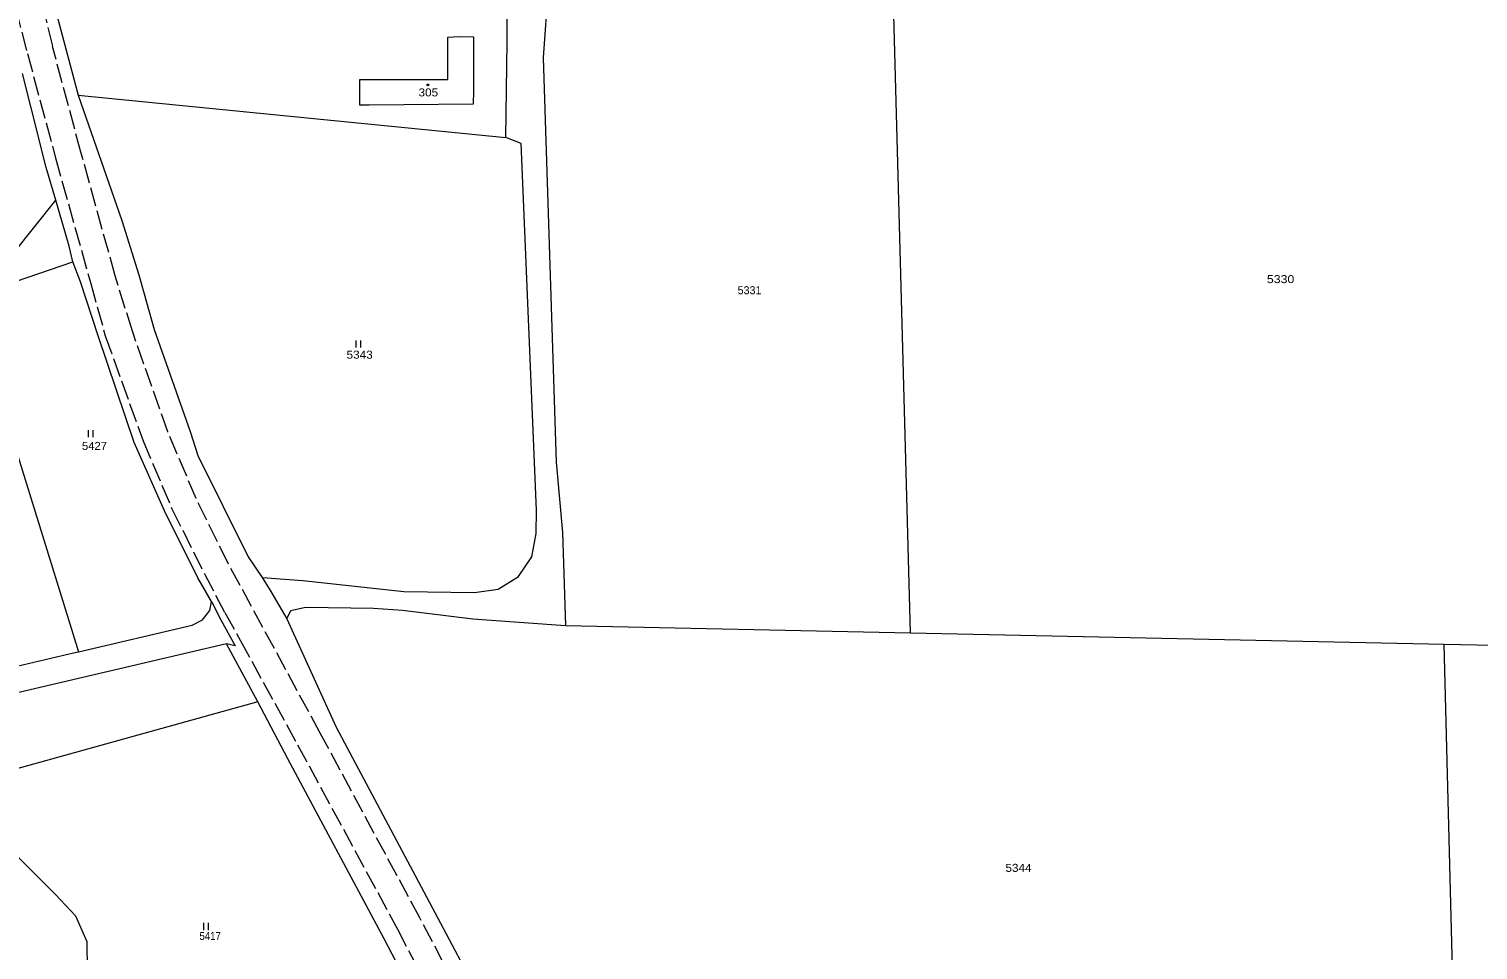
# Model space of a CAD drawing. Extents: x -590528 to -586543, y -1119609 to -1116685.
# Drawn here: x -588671 to -588363.1, y -1118913.5 to -1118717.9 of the extents above; entities that cross this region are included whole.
import ezdxf

# ---------------------------------------------------------------- set-up
doc = ezdxf.new("R2010")
doc.units = 0
doc.header["$LTSCALE"] = 0.68
doc.linetypes.add('LONG_DASHED', pattern=[7.5, 6, -1.5])
for name, color, linetype, lineweight in [('1', 7, 'Continuous', 13), ('2', 7, 'LONG_DASHED', 13), ('3', 7, 'Continuous', 13), ('6', 7, 'Continuous', 13)]:
    doc.layers.add(name, color=color, linetype=linetype, lineweight=lineweight)

msp = doc.modelspace()

# ---------------------------------------------------------------- linework, layer by layer
at = {"layer": '1'}
for p, q in [((-588616.15, -1118843.14), (-588605.69, -1118866.14)), ((-588629, -1118848.43), (-588804.33, -1118889.55)), ((-588483.64, -1118846.11), (-588370.23, -1118848.53)), ((-588367.51, -1118954.3), (-588370.23, -1118848.53)), ((-588370.23, -1118848.53), (-588338.4, -1118849.21)), ((-588622.36, -1118860.76), (-588679.52, -1118876.66))]:
    msp.add_line(p, q, dxfattribs=at)
for points in [[(-588660.52, -1118731.91), (-588569.63, -1118740.9), (-588569.39, -1118720.67), (-588569.35, -1118705.67), (-588569.35, -1118695.79)], [(-588534.05, -1118695.71), (-588549.07, -1118697.08), (-588553.57, -1118697.94), (-588557.37, -1118700.49), (-588559.86, -1118704.34), (-588560.64, -1118708.91), (-588561.74, -1118723.95), (-588558.91, -1118809.84)], [(-588483.64, -1118846.11), (-588487.68, -1118696.41), (-588534.05, -1118695.71)], [(-588669.27, -1118698.89), (-588660.52, -1118731.91), (-588651.24, -1118758.54), (-588647.59, -1118770.04), (-588644.36, -1118781.65)], [(-588683.93, -1118741.34), (-588681.92, -1118748.54), (-588680.14, -1118748.16), (-588678.4, -1118755.05), (-588674.17, -1118765.39), (-588665.28, -1118754.22), (-588667.31, -1118747.26), (-588670.58, -1118734.28), (-588672.35, -1118727.29)], [(-588563.12, -1118820.07), (-588566.39, -1118742.19), (-588569.63, -1118740.9)], [(-588693.35, -1118744.26), (-588683.78, -1118774.9), (-588661.64, -1118767.3), (-588662.44, -1118763.97), (-588665.28, -1118754.22)], [(-588656.16, -1118783.25), (-588660, -1118771.53), (-588661.64, -1118767.3)], [(-588683.78, -1118774.9), (-588660.47, -1118850.13), (-588636.3, -1118844.46)], [(-588635.08, -1118834.44), (-588642.2, -1118820.22), (-588648.61, -1118805.7), (-588656.16, -1118783.25)], [(-588644.36, -1118781.65), (-588636.69, -1118803.36), (-588635.11, -1118808.46), (-588624.36, -1118829.95), (-588621.43, -1118834.37)], [(-588558.91, -1118809.84), (-588557.62, -1118824.8), (-588556.97, -1118844.53), (-588483.64, -1118846.11)], [(-588576.29, -1118837.56), (-588571.25, -1118836.86), (-588566.95, -1118834.17), (-588564.11, -1118829.98), (-588563.22, -1118824.99), (-588563.12, -1118820.07)], [(-588636.3, -1118844.46), (-588634.07, -1118843.36), (-588632.55, -1118841.38), (-588632.16, -1118839.44), (-588635.08, -1118834.44)], [(-588621.43, -1118834.37), (-588612.77, -1118834.98), (-588591.31, -1118837.3), (-588576.29, -1118837.56)], [(-588621.43, -1118834.37), (-588619.58, -1118837.35), (-588616.15, -1118843.14), (-588615.3, -1118841.35), (-588612.18, -1118840.69), (-588597.79, -1118840.85), (-588591.59, -1118841.29), (-588576.66, -1118843.14)], [(-588632.16, -1118839.44), (-588630.19, -1118843.33), (-588627.12, -1118848.84), (-588629, -1118848.43)], [(-588576.66, -1118843.14), (-588573.66, -1118843.35), (-588556.97, -1118844.53)], [(-588615.99, -1118872.87), (-588622.36, -1118860.76), (-588629, -1118848.43)], [(-588678.42, -1118854.34), (-588661.5, -1118850.37), (-588660.47, -1118850.13)], [(-588605.69, -1118866.14), (-588584.73, -1118905.49), (-588575.04, -1118923.76), (-588565.94, -1118942.72)], [(-588570.77, -1118964.45), (-588574.85, -1118952.9), (-588577.99, -1118945.47), (-588579.46, -1118942), (-588586.25, -1118928.74), (-588595.5, -1118911.12), (-588615.99, -1118872.87)], [(-588679.52, -1118876.66), (-588676.15, -1118890.88), (-588665.31, -1118901.67), (-588661.1, -1118906.24), (-588658.66, -1118911.67), (-588658.58, -1118917.9), (-588660.73, -1118923.42), (-588665.2, -1118927.97), (-588671.06, -1118930.31), (-588675.75, -1118934.26), (-588677.28, -1118937.29), (-588677.15, -1118943.53), (-588675.61, -1118949.4), (-588674.47, -1118954.31), (-588671.41, -1118967.19)]]:
    msp.add_lwpolyline(points, dxfattribs=at)
msp.add_lwpolyline([(-588581.98, -1118719.56), (-588579.54, -1118719.45), (-588576.5, -1118719.5), (-588576.53, -1118728.54), (-588576.51, -1118731.01), (-588576.59, -1118733.85), (-588598.67, -1118734.03), (-588600.65, -1118734.04), (-588600.64, -1118728.6), (-588581.99, -1118728.56)], close=True, dxfattribs=at)
at = {"layer": '2'}
msp.add_line((-588670.62, -1118702.66), (-588665.95, -1118721.6), dxfattribs=at)
for points in [[(-588676.35, -1118703.69), (-588671.31, -1118723.03), (-588665.33, -1118745.2), (-588657.84, -1118771.93), (-588654.74, -1118783.01)], [(-588648.99, -1118782.06), (-588652.65, -1118770.25), (-588659.92, -1118744.05), (-588665.95, -1118721.6)], [(-588654.74, -1118783.01), (-588646.71, -1118805.36), (-588640.58, -1118819.77), (-588633.68, -1118833.61), (-588629.36, -1118841.77), (-588626.09, -1118847.67), (-588613.88, -1118869.91)], [(-588609.08, -1118867.4), (-588628.66, -1118831.33), (-588635.46, -1118817.56), (-588641.45, -1118803.44), (-588648.99, -1118782.06)], [(-588563.1, -1118959.73), (-588567.25, -1118948.12), (-588571.87, -1118938.15), (-588578.09, -1118925.28), (-588587.91, -1118906.68), (-588609.08, -1118867.4)], [(-588613.88, -1118869.91), (-588592.67, -1118909.03), (-588583.14, -1118927.27), (-588576.89, -1118939.91), (-588572.09, -1118950.94), (-588568.39, -1118960.93)]]:
    msp.add_lwpolyline(points, dxfattribs=at)
at = {"layer": '6'}
for p, q in [((-588601.43, -1118785.49), (-588601.43, -1118783.99)), ((-588600.43, -1118785.49), (-588600.43, -1118783.99)), ((-588658.3, -1118804.58), (-588658.3, -1118803.08)), ((-588657.3, -1118804.58), (-588657.3, -1118803.08)), ((-588633.8, -1118909.24), (-588633.8, -1118907.74)), ((-588632.8, -1118909.24), (-588632.8, -1118907.74))]:
    msp.add_line(p, q, dxfattribs=at)
msp.add_circle((-588586.2002, -1118729.7204), 0.175, dxfattribs=at)

# ---------------------------------------------------------------- texts
at = {"layer": '3'}
for s, width, p in [('305', 1.1, (-588588.193, -1118732.17)), ('5330', 1.15, (-588407.923, -1118771.83)), ('5343', 1.1, (-588603.483, -1118787.88)), ('5427', 1.05, (-588659.693, -1118807.26)), ('5344', 1.1, (-588463.483, -1118896.88)), ('5417', 0.9, (-588634.733, -1118911.35))]:
    msp.add_text(s, height=1.7, dxfattribs=dict(at, width=width)).set_placement(p)
msp.add_text('5331', height=1.7, dxfattribs=at).set_placement((-588520.383, -1118774.19))

doc.saveas('drawing.dxf')
